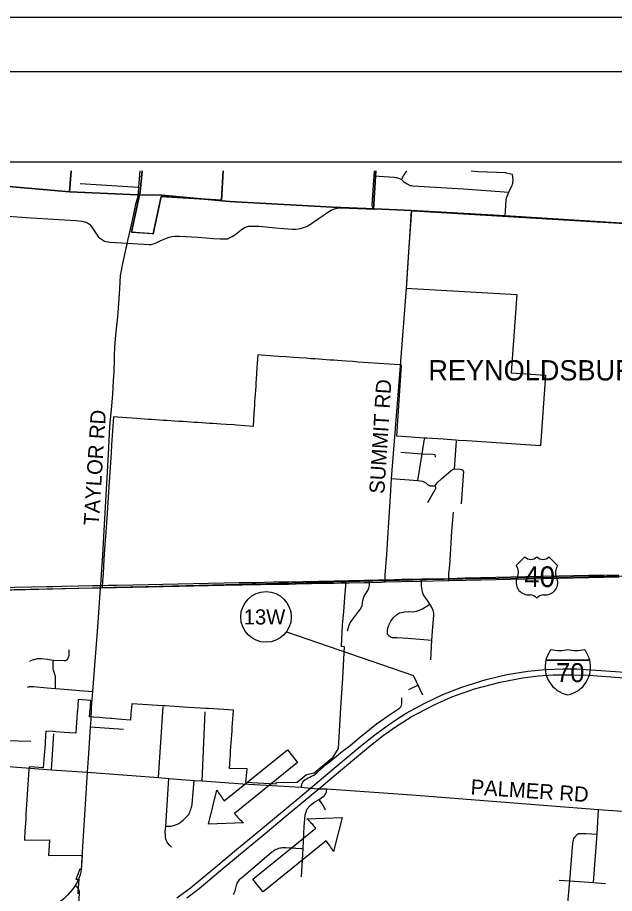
# Model space of a CAD drawing. Extents: x 1880545 to 1948545, y 79309 to 723051.
# Drawn here: x 1890853 to 1901899, y 706837 to 723051 of the extents above; entities that cross this region are included whole.
import ezdxf

# ---------------------------------------------------------------- set-up
doc = ezdxf.new("R2010")
doc.units = 0
for name, color, linetype in [('GM_X_City_Street', 7, 'Continuous'), ('GM_X_Corporation', 7, 'Continuous'), ('GM_X_Corporation_Text', 7, 'Continuous'), ('GM_X_County', 7, 'Continuous'), ('GM_X_Interstate_Route', 7, 'Continuous'), ('GM_X_Interstate_Shield', 7, 'Continuous'), ('GM_X_Rail_Line', 7, 'Continuous'), ('GM_X_Township', 7, 'Continuous'), ('GM_X_Township_Road', 7, 'Continuous'), ('GM_X_US_Route', 7, 'Continuous'), ('GM_X_US_Shield', 7, 'Continuous'), ('SH_Border', 7, 'Continuous'), ('SH_Cut_Line', 7, 'Continuous'), ('SH_Text', 7, 'Continuous')]:
    doc.layers.add(name, color=color, linetype=linetype)

msp = doc.modelspace()

# ---------------------------------------------------------------- linework, layer by layer
at = {"layer": 'GM_X_City_Street'}
for p, q in [((1892015, 719979), (1893094, 719913)), ((1890622, 709667), (1891097, 709658))]:
    msp.add_line(p, q, dxfattribs=at)
for points in [[(1897451, 720118), (1897824, 720093), (1897844, 720091), (1897854, 720092), (1897868, 720088), (1897883, 720086), (1897901, 720078), (1897955, 720055), (1898004, 720009), (1898065, 719974), (1898118, 719944), (1898134, 719942), (1898142, 719940), (1898168, 719936), (1899104, 719880), (1899942, 719819)], [(1897955, 720055), (1897995, 720120), (1898021, 720160), (1898048, 720199), (1898058, 720212)], [(1899246, 720212), (1899379, 720204), (1899880, 720180), (1899894, 720175), (1899953, 720165), (1900009, 720151)], [(1899878, 719375), (1899890, 719570), (1899897, 719670), (1899903, 719715), (1899942, 719819), (1899944, 719826), (1899998, 719930), (1900004, 719942), (1900012, 719964), (1900015, 719983), (1900019, 720005), (1900023, 720045), (1900009, 720151)], [(1892879, 718872), (1893289, 718849), (1893326, 718851), (1893407, 718877), (1893508, 718923), (1893554, 718944), (1893609, 718965), (1893661, 718987), (1893709, 719000), (1893766, 719007), (1893846, 719005), (1894196, 718983), (1894481, 718959), (1894602, 718954), (1894650, 718952), (1894695, 718952), (1894737, 718957), (1894774, 718970), (1894822, 718996), (1894892, 719040), (1894999, 719125), (1895047, 719157), (1895088, 719177), (1895127, 719188), (1895206, 719192), (1895324, 719186), (1895629, 719157), (1895935, 719136), (1895999, 719136), (1896044, 719139), (1896087, 719146), (1896143, 719162), (1896189, 719178), (1896236, 719199), (1896417, 719322), (1896530, 719401), (1896594, 719447), (1896655, 719486), (1896719, 719511), (1896794, 719529), (1896835, 719530), (1897458, 719504)], [(1890151, 719240), (1890216, 719314), (1890263, 719345), (1890295, 719366), (1890370, 719389), (1890418, 719394), (1891105, 719346), (1891930, 719294), (1892041, 719284), (1892095, 719268), (1892147, 719248), (1892183, 719223), (1892219, 719187), (1892352, 718988), (1892405, 718947), (1892463, 718913), (1892561, 718891), (1892879, 718872)], [(1891080, 711135), (1891120, 711153), (1891148, 711166), (1891162, 711170), (1891180, 711176), (1891188, 711176), (1891206, 711180), (1891224, 711184), (1891252, 711184), (1891288, 711184), (1891410, 711177), (1891511, 711157), (1891517, 711157), (1891715, 711148), (1891731, 711148), (1891745, 711150), (1891757, 711154), (1891767, 711162), (1891775, 711170), (1891789, 711196), (1891797, 711212), (1891803, 711230), (1891806, 711242), (1891808, 711264), (1891810, 711280), (1891810, 711300), (1891810, 711344)], [(1891559, 710630), (1891559, 710671), (1891557, 710756), (1891558, 710824), (1891558, 710848), (1891554, 710868), (1891546, 710890), (1891538, 710912), (1891518, 710970), (1891515, 710996), (1891513, 711018), (1891511, 711045), (1891511, 711065), (1891511, 711079), (1891511, 711115), (1891517, 711157)], [(1891035, 710654), (1891054, 710664), (1891074, 710670), (1891086, 710671), (1891106, 710671), (1891149, 710669), (1891401, 710644), (1891559, 710630), (1891563, 710629), (1891789, 710612), (1892002, 710593), (1892240, 710573)]]:
    msp.add_lwpolyline(points, dxfattribs=at)
at = {"layer": 'GM_X_Corporation'}
for points in [[(1897486, 720212), (1897439, 719506), (1897456, 719507), (1898145, 719477), (1898087, 718717), (1898043, 718042), (1900090, 717926), (1899990, 716472), (1900620, 716430), (1900528, 715122), (1899172, 715213), (1899011, 715223), (1898960, 715228), (1898728, 715244), (1898425, 715264), (1898375, 715266), (1898050, 715289), (1897871, 715302), (1897955, 716617), (1897919, 716620), (1897154, 716674), (1897057, 716681), (1896933, 716690), (1896846, 716696), (1896773, 716701), (1896704, 716706), (1896638, 716711), (1896567, 716716), (1896497, 716721), (1896427, 716726), (1896358, 716731), (1896287, 716736), (1896192, 716743), (1896065, 716752), (1895959, 716759), (1895817, 716768), (1895688, 716778), (1895598, 716784), (1895527, 716789), (1895364, 716800), (1895300, 716805), (1895289, 716650), (1895284, 716575), (1895276, 716456), (1895270, 716362), (1895265, 716291), (1895260, 716222), (1895255, 716151), (1895250, 716081), (1895245, 716012), (1895241, 715940), (1895236, 715874), (1895231, 715801), (1895225, 715722), (1895211, 715483), (1894907, 715505), (1894854, 715509), (1894716, 715519), (1894613, 715525), (1894544, 715529), (1894474, 715534), (1894403, 715539), (1894333, 715543), (1894263, 715548), (1894192, 715552), (1894122, 715557), (1894053, 715561), (1893984, 715566), (1893912, 715571), (1893837, 715576), (1893761, 715580), (1893689, 715585), (1893619, 715590), (1893550, 715594), (1893480, 715599), (1893410, 715603), (1893340, 715608), (1893270, 715612), (1893200, 715617), (1893130, 715622), (1893061, 715626), (1892976, 715632), (1892873, 715640), (1892630, 715657), (1892594, 715144), (1892583, 714994), (1892544, 714361), (1892507, 713783), (1892489, 713525), (1892465, 713208), (1892451, 713028), (1892436, 712761), (1892428, 712622), (1892421, 712499), (1892625, 712504), (1892740, 712506), (1892845, 712508), (1892945, 712510), (1893046, 712512), (1893080, 712513), (1893136, 712514), (1893446, 712520), (1893517, 712522), (1893671, 712525), (1893712, 712526), (1893847, 712528), (1894047, 712532), (1894077, 712533), (1894247, 712536), (1894548, 712542), (1894843, 712548), (1895007, 712552), (1895348, 712559), (1896924, 712590), (1896920, 712530), (1896904, 712330), (1896895, 712220), (1896883, 712059), (1896863, 711806), (1896840, 711412), (1896900, 711407), (1896865, 710822), (1896832, 710271), (1896788, 709521), (1896675, 709341), (1896342, 709061), (1896202, 709034), (1896029, 708892), (1895631, 708885), (1895630, 708859), (1895080, 708893), (1895102, 709141), (1894774, 709149), (1894787, 709337), (1894791, 709397), (1894792, 709409), (1894797, 709482), (1894802, 709554), (1894807, 709626), (1894812, 709698), (1894817, 709771), (1894822, 709843), (1894826, 709912), (1894831, 709984), (1894837, 710072), (1894842, 710145), (1894848, 710228), (1894384, 710258), (1894334, 710261), (1893927, 710287), (1893761, 710297), (1893585, 710308), (1893538, 710311), (1893164, 710335), (1892966, 710347), (1892952, 710160), (1892943, 710048), (1892780, 710060), (1892714, 710066), (1892599, 710075), (1892572, 710077), (1892484, 710083), (1892427, 710088), (1892368, 710093), (1892261, 710101), (1892255, 710101), (1892187, 710108), (1892193, 710182), (1892194, 710198), (1892200, 710243), (1892204, 710293), (1892205, 710309), (1892211, 710411), (1892058, 710422), (1891977, 710428), (1891969, 710326), (1891968, 710310), (1891961, 710212), (1891960, 710196), (1891951, 710081), (1891940, 709916), (1891933, 709804), (1891824, 709812), (1891714, 709819), (1891565, 709830), (1891515, 709833), (1891378, 709844), (1891366, 709644), (1891363, 709594), (1891348, 709396), (1891346, 709396), (1891329, 709165), (1891170, 709176), (1891068, 709184), (1891062, 709124), (1891034, 708676), (1891021, 708478), (1891016, 708399), (1891010, 708309), (1891005, 708225), (1891001, 708135), (1890997, 708065), (1890991, 707993), (1890982, 707856), (1890980, 707821), (1891444, 707829), (1891437, 707724), (1891431, 707631), (1891424, 707538), (1892049, 707547), (1892042, 707447), (1892029, 707281), (1892000, 707281), (1891997, 707271), (1891993, 707258), (1891989, 707246), (1891986, 707236), (1891982, 707225), (1891978, 707215), (1891973, 707200), (1891966, 707184), (1891960, 707169), (1891954, 707155), (1891948, 707141), (1891942, 707128), (1891930, 707103), (1891986, 707100), (1891971, 706861), (1891969, 706830)], [(1893159, 720212), (1893124, 719824), (1892964, 719076), (1893344, 719051), (1893361, 719049), (1893513, 719737), (1894629, 719669), (1894660, 720212)], [(1894660, 720212), (1894629, 719669), (1893513, 719737), (1893361, 719049), (1892964, 719076), (1893124, 719824), (1893159, 720212)], [(1919489, 720212), (1919365, 718089), (1918485, 718152), (1917525, 718232), (1914097, 718433), (1913810, 718462), (1910748, 718668), (1904355, 719098), (1898180, 719469), (1898145, 719477), (1897456, 719507), (1897439, 719506), (1897486, 720212)]]:
    msp.add_lwpolyline(points, dxfattribs=at)
at = {"layer": 'GM_X_County'}
msp.add_lwpolyline([(1891843, 720212), (1891817, 719823), (1890200, 719967), (1890150, 719243), (1889940, 716226), (1889896, 715604), (1889789, 714059), (1889789, 714057), (1889728, 713178), (1889728, 713177), (1889680, 712485), (1889677, 712442), (1889513, 710095), (1889456, 709272), (1889272, 706620), (1886741, 706793), (1884485, 706947)], dxfattribs=at)
at = {"layer": 'GM_X_Interstate_Route'}
for points in [[(1893801, 706755), (1894055, 706940), (1894487, 707297), (1894907, 707648), (1895214, 707903), (1895643, 708259), (1896003, 708560), (1896273, 708789), (1896676, 709126), (1897233, 709589), (1897467, 709776), (1897694, 709942), (1897870, 710061), (1898043, 710173), (1898387, 710361), (1898724, 710520), (1899077, 710658), (1899527, 710800), (1899904, 710889), (1900296, 710951), (1900615, 710980), (1900942, 710995), (1901199, 710993), (1901556, 710973), (1902367, 710916)], [(1893987, 706757), (1894214, 706930), (1894687, 707327), (1895085, 707657), (1895398, 707917), (1895823, 708275), (1896188, 708579), (1896426, 708776), (1896830, 709112), (1897386, 709576), (1897620, 709762), (1897830, 709909), (1898135, 710104), (1898563, 710330), (1898887, 710475), (1899309, 710625), (1899781, 710751), (1900200, 710830), (1900488, 710864), (1900763, 710881), (1901124, 710886), (1901417, 710877), (1902079, 710829)]]:
    msp.add_lwpolyline(points, dxfattribs=at)
at = {"layer": 'GM_X_Interstate_Shield'}
for p, q in [((1900630, 711158), (1901442, 711158)), ((1901442, 711158), (1900630, 711158)), ((1901442, 711158), (1900630, 711158))]:
    msp.add_line(p, q, dxfattribs=at)
for centre, start, end in [((1901141, 711029), 141.669, 165.8066), ((1900882, 711860), 253.0091, 286.9909), ((1901190, 711860), 253.0091, 286.9909), ((1900930, 711029), 14.1934, 38.331), ((1901141, 711029), 165.8066, 258.463), ((1900930, 711029), 281.537, 14.1934)]:
    msp.add_arc(centre, 527, start, end, dxfattribs=at)
at = {"layer": 'GM_X_Rail_Line'}
msp.add_lwpolyline([(1889656, 712431), (1890757, 712458), (1898417, 712647), (1903434, 712741), (1904816, 712771), (1913576, 712916), (1914801, 712916), (1920019, 712995), (1921942, 713063), (1924553, 713124), (1928206, 713206)], dxfattribs=at)
at = {"layer": 'GM_X_Township'}
for points in [[(1891843, 720212), (1891817, 719823), (1890200, 719967), (1886445, 720189), (1886104, 720212)], [(1919533, 720212), (1919387, 718085), (1918485, 718152), (1917525, 718232), (1914126, 718466), (1913826, 718485), (1910749, 718688), (1904377, 719099), (1899877, 719378), (1898145, 719477), (1897456, 719507), (1896834, 719533), (1896793, 719532), (1894775, 719644), (1893522, 719763), (1893081, 719771), (1891817, 719823), (1891843, 720212)], [(1889272, 706620), (1889456, 709272), (1889513, 710095), (1889677, 712442), (1889680, 712485), (1889728, 713177), (1889728, 713178), (1889789, 714057), (1889789, 714059), (1889896, 715604), (1889940, 716226), (1890150, 719243), (1890200, 719967), (1891817, 719823), (1893081, 719771), (1893522, 719763), (1894775, 719644), (1896793, 719532), (1896834, 719533), (1897456, 719507), (1898145, 719477), (1899877, 719378), (1904377, 719099)]]:
    msp.add_lwpolyline(points, dxfattribs=at)
at = {"layer": 'GM_X_Township_Road'}
for p, q in [((1898146, 719475), (1897458, 719504)), ((1898940, 714695), (1898974, 715207)), ((1892219, 710269), (1892207, 710066)), ((1893463, 708982), (1893548, 710290)), ((1894267, 708922), (1894327, 710199)), ((1892815, 709875), (1892198, 709913)), ((1891479, 709125), (1891527, 709794)), ((1892038, 707383), (1892030, 707278))]:
    msp.add_line(p, q, dxfattribs=at)
for points in [[(1893118, 720212), (1893094, 719913), (1893093, 719905), (1893086, 719803), (1893083, 719768), (1893079, 719754)], [(1897458, 719504), (1897438, 719522), (1897423, 719547), (1897418, 719584), (1897451, 720118), (1897457, 720212)], [(1893079, 719754), (1893071, 719726), (1893065, 719695), (1893037, 719591), (1893020, 719501), (1892999, 719413), (1892955, 719215), (1892917, 719055), (1892891, 718921), (1892879, 718872), (1892857, 718784), (1892834, 718666), (1892796, 718496), (1892776, 718398), (1892755, 718278), (1892738, 718034), (1892722, 717755), (1892703, 717513), (1892667, 717175), (1892650, 716952), (1892642, 716790)], [(1897938, 716605), (1898056, 718119), (1898146, 719475)], [(1904378, 719096), (1899878, 719375), (1898146, 719475)], [(1892642, 716790), (1892641, 716780), (1892639, 716738), (1892636, 716483), (1892626, 716333), (1892611, 716075), (1892585, 715793), (1892557, 715478), (1892534, 715094), (1892524, 714858), (1892445, 713443), (1892423, 713092), (1892400, 712744), (1892386, 712539), (1892381, 712495)], [(1897656, 712603), (1897656, 712645), (1897658, 712730), (1897686, 713112), (1897712, 713521), (1897734, 713894), (1897759, 714296), (1897776, 714517), (1897938, 716605)], [(1898258, 714484), (1898343, 714977), (1898386, 715255)], [(1897947, 715006), (1898343, 714977), (1898544, 714969), (1898576, 714961), (1898582, 714915)], [(1897776, 714517), (1898258, 714484), (1898347, 714470), (1898373, 714458), (1898416, 714429), (1898446, 714404), (1898467, 714393), (1898486, 714384), (1898527, 714381), (1898553, 714384), (1898581, 714391), (1898620, 714436), (1898704, 714520), (1898872, 714661), (1898899, 714683), (1898940, 714695), (1899048, 714691), (1899076, 714685), (1899101, 714666)], [(1899066, 714051), (1899105, 714572), (1899110, 714641), (1899101, 714666)], [(1898448, 714073), (1898584, 714312), (1898594, 714330), (1898594, 714350), (1898581, 714391)], [(1898831, 712628), (1898831, 712670), (1898836, 712756), (1898852, 712916), (1898871, 713217), (1898891, 713546), (1898920, 713892)], [(1896959, 711699), (1896989, 711801), (1897008, 711847), (1897038, 711892), (1897151, 712039), (1897193, 712094), (1897215, 712134), (1897229, 712171), (1897237, 712210), (1897243, 712261), (1897252, 712301), (1897266, 712338), (1897292, 712376), (1897338, 712444), (1897355, 712489), (1897364, 712540), (1897367, 712596), (1897367, 712638)], [(1898498, 711163), (1898520, 711527), (1898540, 711775), (1898556, 711980), (1898556, 712026), (1898546, 712072), (1898512, 712140), (1898480, 712192), (1898424, 712276), (1898388, 712328), (1898362, 712379), (1898347, 712416), (1898332, 712486), (1898328, 712531), (1898330, 712618), (1898332, 712660)], [(1892381, 712495), (1892338, 711851), (1892240, 710573), (1892224, 710351), (1892219, 710269)], [(1897722, 711612), (1897700, 711637), (1897697, 711678), (1897699, 711711), (1897720, 711791), (1897763, 711878), (1897803, 711937), (1897864, 711997), (1897924, 712030), (1898021, 712053), (1898091, 712055), (1898171, 712053), (1898233, 712062), (1898346, 712104), (1898480, 712192)], [(1897722, 711612), (1897754, 711589), (1897786, 711576), (1897871, 711573), (1898075, 711560), (1898520, 711527)], [(1896101, 708804), (1896111, 708850), (1896119, 708875), (1896139, 708917), (1896175, 708948), (1896203, 708962), (1896229, 708976), (1896263, 708989), (1896295, 709009), (1896322, 709023), (1896352, 709042), (1896404, 709084), (1896568, 709228), (1896719, 709350), (1896865, 709471), (1897008, 709579), (1897177, 709717), (1897363, 709873), (1897496, 709976), (1897573, 710035), (1897680, 710106), (1897811, 710194), (1897905, 710253), (1897924, 710267), (1897944, 710293), (1897960, 710314), (1897967, 710348), (1897962, 710461)], [(1892207, 710066), (1892198, 709913), (1892166, 709426), (1892142, 709082)], [(1890133, 709225), (1890143, 709225), (1890599, 709192), (1891013, 709160)], [(1891013, 709160), (1891479, 709125), (1892142, 709082)], [(1892142, 709082), (1892039, 707404), (1892038, 707383)], [(1892142, 709082), (1893463, 708982), (1893651, 708968), (1894121, 708931), (1894267, 708922), (1895024, 708865), (1896101, 708804), (1896273, 708789), (1896426, 708776), (1896575, 708772), (1898149, 708664), (1901603, 708394), (1902483, 708331), (1903856, 708249)], [(1893704, 707693), (1893672, 707722), (1893637, 707768), (1893623, 707788), (1893605, 707825), (1893598, 707845), (1893592, 707877), (1893589, 707909), (1893587, 707979), (1893597, 708084), (1893651, 708968)], [(1893597, 708084), (1893687, 708084), (1893719, 708092), (1893793, 708113), (1893825, 708127), (1893861, 708152), (1893896, 708178), (1893916, 708194), (1893936, 708214), (1893956, 708231), (1893978, 708253), (1893999, 708277), (1894021, 708297), (1894031, 708319), (1894042, 708342), (1894050, 708364), (1894062, 708394), (1894068, 708418), (1894079, 708456), (1894085, 708488), (1894121, 708931)], [(1896106, 707148), (1896141, 707668), (1896155, 708077), (1896167, 708213), (1896175, 708291), (1896194, 708349), (1896215, 708402), (1896267, 708465), (1896337, 708519), (1896436, 708576), (1896532, 708650), (1896555, 708689), (1896571, 708727), (1896575, 708772)], [(1896554, 708379), (1896512, 708457), (1896436, 708576)], [(1901512, 707040), (1901579, 707932), (1901603, 708394)], [(1900989, 705810), (1901020, 706446), (1901071, 707072), (1901129, 707767), (1901132, 707790), (1901134, 707806), (1901140, 707824), (1901148, 707852), (1901158, 707872), (1901172, 707888), (1901182, 707900), (1901198, 707920), (1901212, 707932), (1901234, 707947), (1901266, 707949), (1901286, 707949), (1901312, 707949), (1901370, 707947), (1901579, 707932)], [(1894851, 706817), (1894860, 706838), (1894870, 706862), (1894878, 706888), (1894904, 706987), (1894911, 707009), (1894917, 707025), (1894927, 707046), (1894940, 707066), (1894952, 707083), (1894965, 707099), (1894979, 707112), (1894997, 707129), (1895417, 707482), (1895555, 707599), (1895576, 707615), (1895596, 707630), (1895617, 707643), (1895638, 707654), (1895662, 707665), (1895685, 707673), (1895710, 707679), (1895732, 707684), (1895757, 707687), (1895786, 707688), (1895818, 707687), (1896093, 707670), (1896141, 707668)], [(1892030, 707278), (1892021, 707209), (1892007, 707165), (1891987, 707113), (1891971, 707079)], [(1891971, 707079), (1891958, 707049), (1891919, 706984), (1891900, 706953), (1891859, 706896), (1891779, 706807), (1891715, 706743), (1891650, 706686), (1891590, 706646), (1891388, 706525), (1891303, 706473)], [(1891990, 706909), (1891984, 706923), (1891966, 706947), (1891952, 706960), (1891935, 706972), (1891919, 706984)], [(1900873, 707086), (1901071, 707072), (1901512, 707040), (1901731, 707024)], [(1891975, 706450), (1891998, 706836), (1891998, 706870), (1891993, 706900), (1891990, 706909)]]:
    msp.add_lwpolyline(points, dxfattribs=at)
at = {"layer": 'GM_X_US_Route'}
msp.add_line((1896843, 712585), (1896906, 712586), dxfattribs=at)
for points in [[(1892386, 712539), (1892538, 712542), (1892684, 712545), (1892990, 712552), (1893271, 712558), (1893545, 712564), (1893828, 712569), (1894110, 712574), (1894390, 712580), (1894675, 712585), (1894949, 712591), (1895257, 712596), (1895588, 712603), (1895869, 712608), (1896136, 712613), (1896424, 712619), (1896710, 712625), (1896991, 712631), (1897272, 712637), (1897367, 712638)], [(1896906, 712586), (1896991, 712588), (1897272, 712594), (1897367, 712596), (1897586, 712601), (1897656, 712603), (1897949, 712609), (1898330, 712618), (1898547, 712622), (1898831, 712628), (1899148, 712635), (1899425, 712641), (1899707, 712647), (1899983, 712653), (1900267, 712660), (1900587, 712665), (1900867, 712672), (1901145, 712679), (1901425, 712684), (1901705, 712690), (1901985, 712695)], [(1897367, 712638), (1897535, 712642), (1897656, 712645), (1897831, 712648), (1897973, 712652), (1898332, 712660), (1898547, 712664), (1898831, 712670), (1899139, 712677), (1899419, 712683), (1899701, 712689), (1899982, 712695), (1900262, 712702), (1900588, 712708), (1900863, 712714), (1901142, 712720), (1901424, 712726), (1901704, 712732), (1901982, 712737)], [(1889678, 712440), (1890271, 712452), (1890446, 712455), (1890795, 712464), (1891094, 712470)], [(1889681, 712482), (1890269, 712494), (1890450, 712499), (1890799, 712508), (1891114, 712515), (1891398, 712520), (1891508, 712522)], [(1891094, 712470), (1891110, 712470), (1891393, 712476), (1891506, 712478)], [(1891506, 712478), (1891675, 712481), (1891970, 712487), (1892242, 712493), (1892381, 712495)], [(1891508, 712522), (1891680, 712525), (1891974, 712531), (1892246, 712537), (1892386, 712539)], [(1892381, 712495), (1892684, 712502), (1892990, 712509), (1893271, 712515), (1893377, 712517)], [(1893377, 712517), (1893546, 712521), (1893828, 712526), (1894110, 712531), (1894390, 712537), (1894671, 712544), (1894949, 712548), (1895267, 712554), (1895589, 712560), (1895869, 712565), (1896152, 712572), (1896430, 712578), (1896711, 712583), (1896843, 712585)]]:
    msp.add_lwpolyline(points, dxfattribs=at)
at = {"layer": 'GM_X_US_Shield'}
for p, q in [((1900241, 713068), (1900081, 712908)), ((1900847, 712908), (1900687, 713068)), ((1900304, 712366), (1900336, 712366)), ((1900592, 712366), (1900624, 712366))]:
    msp.add_line(p, q, dxfattribs=at)
for centre, radius, start, end in [((1900352, 713181), 160, 225.573, 314.427), ((1900576, 713181), 160, 225.573, 314.427), ((1899898, 712780), 223, 334.5471, 35.0009), ((1901030, 712780), 223, 144.9991, 205.4529), ((1900302, 712589), 223, 154.8319, 270.6383), ((1900626, 712589), 223, 269.3617, 25.1681), ((1900336, 712206), 160, 36.8699, 90), ((1900592, 712206), 160, 90, 143.1301)]:
    msp.add_arc(centre, radius, start, end, dxfattribs=at)
at = {"layer": 'SH_Border'}
msp.add_lwpolyline([(1883545, 722051), (1947545, 722051), (1947545, 680051), (1883545, 680051)], close=True, dxfattribs=at)
at = {"layer": 'SH_Cut_Line'}
msp.add_lwpolyline([(1880545, 679051), (1948545, 679051), (1948545, 723051), (1880545, 723051)], close=True, dxfattribs=at)
at = {"layer": 'SH_Text'}
for p, q in [((1895830, 711682), (1898181, 710871)), ((1898352, 710509), (1898181, 710871)), ((1898267, 710690), (1898086, 710605)), ((1894679, 708552), (1895846, 709494)), ((1895846, 709494), (1895940, 709378)), ((1896034, 709261), (1894868, 708318)), ((1895940, 709378), (1896034, 709261)), ((1894384, 708121), (1894543, 708751)), ((1895034, 708144), (1894384, 708121)), ((1896209, 708219), (1896858, 708242)), ((1896858, 708242), (1896699, 707612)), ((1895208, 707101), (1896375, 708044)), ((1896563, 707811), (1895397, 706868)), ((1895302, 706985), (1895208, 707101)), ((1895397, 706868), (1895302, 706985))]:
    msp.add_line(p, q, dxfattribs=at)
msp.add_lwpolyline([(1884490, 720381), (1928141, 720381), (1928141, 691152), (1884490, 691152)], close=True, dxfattribs=at)
msp.add_circle((1895451, 711956), 468, dxfattribs=at)
for centre, start, end in [((1895846, 709494), 209.7219, 218.9386), ((1896034, 709261), 218.9386, 228.1552), ((1895208, 707101), 38.9386, 48.1552), ((1895397, 706868), 29.7219, 38.9386)]:
    msp.add_arc(centre, 1500, start, end, dxfattribs=at)

# ---------------------------------------------------------------- texts
at = {"layer": 'GM_X_Corporation_Text'}
msp.add_text('REYNOLDSBURG', height=375, rotation=0, dxfattribs=at).set_placement((1898455, 716334))
at = {"layer": 'GM_X_Interstate_Shield'}
msp.add_text('70', height=351.6, dxfattribs=at).set_placement((1900820, 710749))
at = {"layer": 'GM_X_US_Shield'}
msp.add_text('40', height=382.9, dxfattribs=at).set_placement((1900229, 712509))
at = {"layer": 'SH_Text'}
for s, rotation, p in [('SUMMIT RD', 86.4008, (1897640, 714229)), ('TAYLOR RD', 86.4008, (1892356, 713642)), ('PALMER RD', 356.2172, (1899231, 708672))]:
    msp.add_text(s, height=280, rotation=rotation, dxfattribs=at).set_placement(p)
msp.add_text('13W', height=280, dxfattribs=at).set_placement((1895038, 711816))

doc.saveas('drawing.dxf')
